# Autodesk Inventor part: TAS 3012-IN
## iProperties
Company: RingFeder Corp
Author: Alan
Shininess: 25.0
PropertySet Name: _Private Model Information
Created: 2001-02
Part Number: TAS 3012-IN
Document SubType Name: Modeling
Designer: Alan
Description: 1 TAS 3012-IN
Vendor: RingFeder Corp
Material: Steel, Mild
Control State: 0
Master: False
Checked Out: False
PropertySet Name: Design Tracking Control
Density: 7.860000000000001
Volumn: 178.46094438810258
Area: 682.5564180572235
PropertySet Name: Model Information
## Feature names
1. Revolution1
2. Revolution2
3. Extrusion1
4. Extrusion2
5. Chamfer1
6. Extrusion3
7. Circular Pattern1
